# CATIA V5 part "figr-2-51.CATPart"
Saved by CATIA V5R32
Part number: Part1
Bounding box of the stored display mesh (mm): x -69.981 to 69.981, y -240 to 0, z -69.908 to 69.908
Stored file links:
  D:\PROJECTS\Project 2022\CATIA V5 6R 2022\Resources\Part Files\c02_catia_v5_6r2022_prt\figr-2-51.CATPart
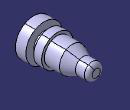
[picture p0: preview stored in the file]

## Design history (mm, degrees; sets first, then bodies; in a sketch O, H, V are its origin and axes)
Body1 (main body)
  Sketch1 on yz-plane, origin (0, 0, 0), H (0, 1, 0), V (0, 0, 1)
    line L1 (0, 0) -> (0, 15.359)
    arc A1 centre (-15.359, 15.359) radius 15.359 from (0, 15.359) to (-15.359, 30.718) ccw
    point P2 (-15.359, 15.359)
    line L2 (-15.359, 30.718) -> (-49.6877, 30.718)
    line L3 (-49.6877, 30.718) -> (-91.8922, 49.6007)
    line L4 (-91.8922, 49.6007) -> (-149.3038, 49.6007)
    line L5 (-149.3038, 49.6007) -> (-149.3038, 60)
    line L6 (-149.3038, 60) -> (-180, 60)
    line L7 (-180, 60) -> (-180, 38.9967)
    line L8 (-180, 38.9967) -> (-200, 40)
    line L9 (-200, 40) -> (-200, 70)
    line L10 (-200, 70) -> (-240, 70)
    line L11 (-240, 70) -> (-240, 0)
    line L12 (-240, 0) -> (0, 0)
    axis line L13 (-300, 0) -> (50, 0)
    vertical: L1 V, L5 V, L7 V, L9 V, L11 V
    tangency: A1 L1, L2 A1, L8 A1, L12 A1, L13 A1
    coincidence: L3 P2
    horizontal: L4 H, L6 H, L10 H, L2 H
    fix: L12
  Shaft1: profile Sketch1, axis Sketch1.H, angle 360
